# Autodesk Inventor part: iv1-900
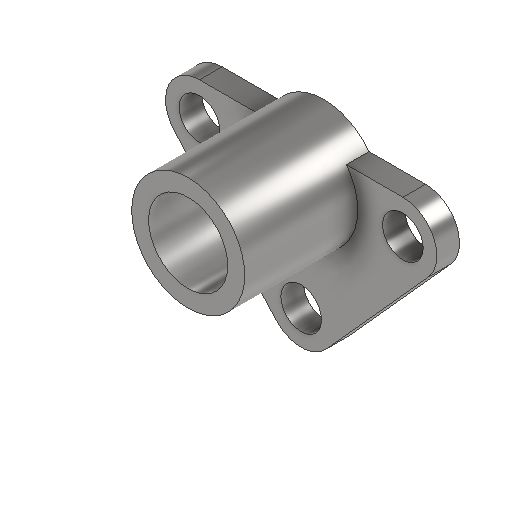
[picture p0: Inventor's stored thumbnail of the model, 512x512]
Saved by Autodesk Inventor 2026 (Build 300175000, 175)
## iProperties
Created: 2022-01
Part Number: iv1-900
Material: Steel, Mild
Document SubType Name: Modeling
Designer: Lars Bertram Pedersen
Density: 7.85 g/cm^3
Appearance: Semi-Polished
Author: Lars Bertram Pedersen
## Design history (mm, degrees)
sketch "Sketch1"
  geometry: L1 (56.149, -10.034)-(11.149, -60.034); L2 (-11.149, -60.034)-(-56.149, -10.034); L3 (-45, 15)-(-20, 15); L4 (20, 15)-(45, 15); C1 r 9 at (-45, 0); C2 r 9 at (0, -50); C3 r 9 at (45, 0); C4 r 17.5 at (0, 0); A1 r 25 centre (0, 0) between (20, 15) and (-20, 15); A2 r 15 centre (-45, 0) between (-45, 15) and (-56.149, -10.034); A3 r 15 centre (45, 0) between (56.149, -10.034) and (45, 15); A4 r 15 centre (0, -50) between (-11.149, -60.034) and (11.149, -60.034); 3 further points
  constraints: 8 centre point, 8 end point, 8 point on circle, 6 tangent, 5 coincident, 4 equal radius, 4 point on line, 2 equal length, 2 horizontal, 1 collinear, 1 horizontal alignment
  dimensions: "d1" = 15 radius of A2; "d2" = 25 radius of A1; "d3" = 50 distance of A4.centre point (0, 0); "d4" = 90 distance of A3.centre A2.centre; "d5" = 18 diameter of C2; "d6" = 35 diameter of C4
extrude "Extrusion1" new body sketch "Sketch1" distance "d7" = 10; taper "d8" = 0 deg
sketch "Sketch2"
  geometry: C1 r 17.5 at (0, 0) reference; A1 r 25 centre (0, 0) between (20, 15) and (-20, 15) reference; 3 further points
  constraints: 1 coincident, 3 other
extrude "Extrusion2" join sketch "Sketch2" distance "d9" = 50; taper "d10" = 0 deg
body "Solid1"
